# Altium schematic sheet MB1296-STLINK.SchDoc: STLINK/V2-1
size A4; Date: 25-JAN-2017; DocumentNumber: MB1296; Revision: D-01; SheetNumber: 3; SheetTotal: 6; Project: STM32 LoRa Discovery
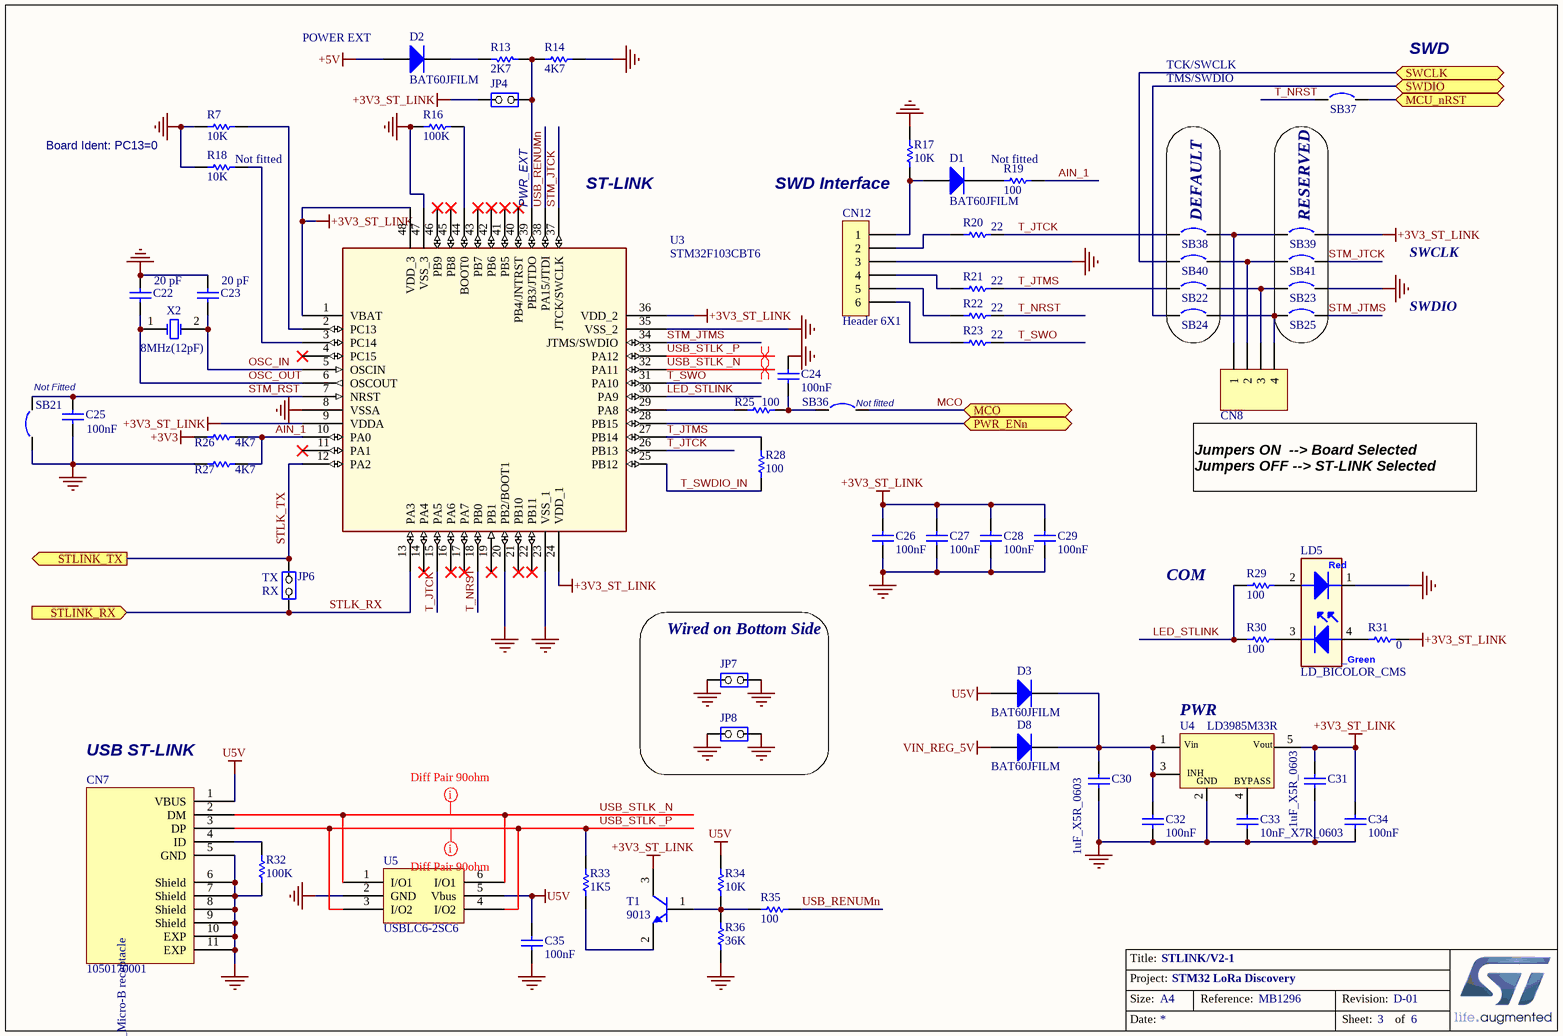
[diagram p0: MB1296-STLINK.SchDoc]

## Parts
C22  20 pF  [0603C]
C23  20 pF  [0603C]
C24  100nF  [0603C]
C25  100nF  [0603C]
C26  100nF  [0603C]
C27  100nF  [0603C]
C28  100nF  [0603C]
C29  100nF  [0603C]
C30  1uF_X5R_0603  [0603C]
C31  1uF_X5R_0603  [0603C]
C32  100nF  [0603C]
C33  10nF_X7R_0603  [0603C]
C34  100nF  [0603C]
C35  100nF  [0603C]
CN7  1050170001  [Molex_1050170001]
CN8  Header 4  [SIP4]  (value not drawn)
CN12  Header 6X1  [Header 1x6 Female (Wrapping)]
D1  BAT60JFILM  [SOD323/A]
D2  BAT60JFILM  [SOD323/A]
D3  BAT60JFILM  [SOD323/A]
D8  BAT60JFILM  [SOD323/A]
JP4  (no value)  [SIP2/2.54]
JP6  (no value)  [SIP2/2.54]
JP7  (no value)  [SIP2/2.54-BOT]
JP8  (no value)  [SIP2/2.54-BOT]
LD5  LD_BICOLOR_CMS  [LED SMD HSMF-A201-A00J1]
R7  10K  [0603]
R13  2K7  [0603]
R14  4K7  [0603]
R16  100K  [0603]
R17  10K  [0603]
R18  10K  [0603]
R19  100  [0603]
R20  22  [0603]
R21  22  [0603]
R22  22  [0603]
R23  22  [0603]
R25  100  [0603]
R26  4K7  [0603]
R27  4K7  [0603]
R28  100  [0603]
R29  100  [0603]
R30  100  [0603]
R31  0  [0603]
R32  100K  [0603]
R33  1K5  [0603]
R34  10K  [0603]
R35  100  [0603]
R36  36K  [0603]
SB21  Circuit Breaker  [JP2_SMD]  (value not drawn)
SB22  Circuit Breaker  [JP2_SMD]  (value not drawn)
SB23  Circuit Breaker  [SB-tiny]  (value not drawn)
SB24  Circuit Breaker  [JP2_SMD]  (value not drawn)
SB25  Circuit Breaker  [SB-tiny]  (value not drawn)
SB36  Circuit Breaker  [JP2_SMD]  (value not drawn)
SB37  Circuit Breaker  [JP2_SMD]  (value not drawn)
SB38  Circuit Breaker  [JP2_SMD]  (value not drawn)
SB39  Circuit Breaker  [SB-tiny]  (value not drawn)
SB40  Circuit Breaker  [JP2_SMD]  (value not drawn)
SB41  Circuit Breaker  [SB-tiny]  (value not drawn)
T1  9013  [SOT-23]
U3  STM32F103CBT6  [QFP48 7X7]
U4  LD3985M33R  [SOT-23-5L]
U5  USBLC6-2SC6  [SOT23-6L]
X2  8MHz(12pF)  [CRY_NX3225GD_2P]

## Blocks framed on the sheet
DEFAULT: SB22 SB24 SB38 SB40
RESERVED: SB23 SB25 SB39 SB41
Wired on Bottom Side: JP7 JP8

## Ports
MCO, MCU_nRST, PWR_ENn (bidir), STLINK_RX (in), STLINK_TX (out), SWCLK, SWDIO

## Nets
+3V3: R26.1
+3V3_ST_LINK: C26.2 C27.2 C28.2 C29.2 C31.2 C34.2 JP4.1(COMMON) R31.2 SB39.2 T1.3(C) U3.1(VBAT) U3.9(VDDA) U3.24(VDD_1) U3.36(VDD_2) U3.48(VDD_3) U4.5(Vout)
+5V: D2.1(A)
GND: C22.2 C23.2 C24.2 C25.1 C26.1 C27.1 C28.1 C29.1 C30.1 C31.1 C32.1 C33.1 C34.1 C35.1 CN7.5(GND) CN7.6(Shield) CN7.7(Shield) CN7.8(Shield) CN7.9(Shield) CN7.10(EXP) CN7.11(EXP) CN12.3 JP7.1(COMMON) JP7.2(NO) JP8.1(COMMON) JP8.2(NO) LD5.1 R7.2 R14.2 R16.2 R17.1 R18.2 R27.1 R32.1 R36.1 SB21.1 SB23.2 U3.8(VSSA) U3.20(PB2/BOOT1) U3.23(VSS_1) U3.35(VSS_2) U3.47(VSS_3) U4.2(GND) U5.2(GND)
U5V: C35.2 CN7.1(VBUS) D3.1(A) R34.1 U5.5(Vbus)
VIN_REG_5V: D8.1(A)
AIN_1: R19.1 R26.2 R27.2 U3.10(PA0)
LED_STLINK: R29.2 R30.2 U3.30(PA9)
MCO: SB36.2 ; port MCO
MCU_nRST: SB37.2 ; port MCU_nRST
OSC_IN: C23.1 U3.5(OSCIN) X2.2(OSC2)
OSC_OUT: C22.1 U3.6(OSCOUT) X2.1(OSC1)
PWR_ENn: U3.28(PB15) ; port PWR_ENn
STLK_RX: JP6.1(COMMON) U3.13(PA3) ; port STLINK_RX
STLK_TX: JP6.2(NO) U3.12(PA2) ; port STLINK_TX
STM_JTCK: SB41.2 U3.37(JTCK/SWCLK)
STM_JTMS: SB25.2 U3.34(JTMS/SWDIO)
STM_RST: C25.2 SB21.2 U3.7(NRST)
SWCLK: SB40.1 ; port SWCLK
SWDIO: SB24.1 ; port SWDIO
T_JTCK: R20.1 SB38.1 U3.15(PA5) U3.26(PB13)
T_JTMS: R21.1 R28.2 SB22.1 U3.27(PB14)
T_NRST: R22.1 SB37.1 U3.18(PB0)
T_SWDIO_IN: R28.1 U3.25(PB12)
T_SWO: R23.1 U3.31(PA10)
USB_RENUMn: R35.1 U3.38(PA15/JTDI)
USB_STLK _N: CN7.2(DM) U3.32(PA11) U5.1(I/O1) U5.6(I/O1)
USB_STLK _P: CN7.3(DP) R33.2 U3.33(PA12) U5.3(I/O2) U5.4(I/O2)
NetC24_1: C24.1 R25.1 SB36.1
NetC30_2: C30.2 C32.2 D3.2(K) D8.2(K) U4.1(Vin) U4.3(CE)
NetC33_2: C33.2 U4.4(BYPASS)
NetCN7_4: CN7.4(ID) R32.2
NetCN8_1: CN8.1 SB38.2 SB39.1
NetCN8_2: CN8.2 SB40.2 SB41.1
NetCN8_3: CN8.3 SB22.2 SB23.1
NetCN8_4: CN8.4 SB24.2 SB25.1
NetCN12_1: CN12.1 D1.1(A) R17.2
NetCN12_2: CN12.2 R20.2
NetCN12_4: CN12.4 R21.2
NetCN12_5: CN12.5 R22.2
NetCN12_6: CN12.6 R23.2
NetD1_2: D1.2(K) R19.2
NetD2_2: D2.2(K) R13.1
NetJP4_2: JP4.2(NO) R13.2 R14.1 U3.39(PB3/JTDO)
NetLD5_2: LD5.2 R29.1
NetLD5_3: LD5.3 R30.1
NetLD5_4: LD5.4 R31.1
NetR7_1: R7.1 U3.2(PC13)
NetR16_1: R16.1 U3.44(BOOT0)
NetR18_1: R18.1 U3.3(PC14)
NetR25_2: R25.2 U3.29(PA8)
NetR33_1: R33.1 T1.2(E)
NetR34_2: R34.2 R35.2 R36.2 T1.1(B)

Not connected (* = marked no-connect by the designer): U3 4(PC15)* 11(PA1)* 14(PA4)* 16(PA6)* 17(PA7)* 19(PB1)* 21(PB10)* 22(PB11)* 40(PB4/JNTRST)* 41(PB5)* 42(PB6)* 43(PB7)* 45(PB8)* 46(PB9)*

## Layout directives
differential pair: USB_STLK _N, USB_STLK _P
mark named Diff Pair 90ohm: USB_STLK _N, USB_STLK _P

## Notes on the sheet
- POWER EXT
- TCK/SWCLK
- TMS/SWDIO
- SWD
- Board Ident: PC13=0
- (near R18) Not fitted
- (near R19) Not fitted
- (near U3) PWR_EXT
- ST-LINK
- SWD Interface
- SWCLK
- SWDIO
- Not Fitted
- (near SB36) Not fitted
- Jumpers ON  --> Board Selected
  Jumpers OFF --> ST-LINK Selected
- (near JP6) TX
- COM
- (near JP6) RX
- (near U4) PWR
- (near CN7) USB ST-LINK

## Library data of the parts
C22 C23 = Capacitor_ST: Capacitor 0603; Manufacturer: YAGEO; Manufacturer P/N: CC0603JRNPO9BN200; Value: 20pF; Provided by: Subcon
C24-C29 C32 C34 C35 = CAP: Capacitor 100nF; Manufacturer: YAGEO; Manufacturer P/N: CC0603KRX7R9BB104; Provided by: Subcon
C30 C31 = CAP SMD 0603  X5R 1µF 25V 10%: 0603  X5R 1µF; Manufacturer: YAGEO; Manufacturer P/N: CC0603KRX5R7BB105; Provided by: Subcon
C33 = CAP SMD 0603  X7R 10000PF 50V 10%: 0603  X7R 10NF; Manufacturer: YAGEO; Manufacturer P/N: CC0603KRX7R9BB103; Order code RS: 2040779; Provided by: Subcon
CN7 = 1050170001: Silkscreen: USB
CN8 = Header 4: Header, 4-Pin, Single row; Manufacturer: Lyconn; Manufacturer P/N: 313140S111116; Provided by: Subcon
CN12 = Header 6X1: Header, 6-Pin, Single row; Manufacturer: Lyconn; Manufacturer P/N: 218106S1610; Provided by: Subcon
D1-D3 D8 = BAT60JFILM: Manufacturer: STM; ECCN_US/EU: EAR99/NEC; Provided by: ST
JP4 JP6-JP8 = JP2: Manufacturer: Lyconn; Manufacturer P/N: 313140S111116; Provided by: Subcon
LD5 = LD_BICOLOR_CMS: Bicolor Led; Manufacturer: everluck-led; Manufacturer P/N: LE-RGW35280; Provided by: Subcon
R7 R17 R34 = Resistor_ST: Resistor 0603; Manufacturer: YAGEO; Manufacturer P/N: RC0603JR-0710KL; Provided by: Subcon
R13 R36 = Res1: Resistor; Value: 1K
R14 R26 R27 = res1_4: Resistor; Manufacturer: YAGEO; Manufacturer P/N: RC0603FR-074K7L; Provided by: Subcon
R16 R32 = RES SMD 0603 100K 75V 5% 0.1W: 0603 100K 75V 5% 0.1W; Manufacturer: YAGEO; Manufacturer P/N: RC0603FR-07100KL; Provided by: Subcon
R18 = Resistor_ST: Resistor 0603; Manufacturer: YAGEO; Manufacturer P/N: RC0603JR-0710KL; Fitted: No; Provided by: Subcon
R19 = Res1_1: Resistor 0603; Manufacturer: YAGEO; Manufacturer P/N: RC0603FR-07100RL; Fitted: No; Provided by: Subcon; Value: 100R
R20-R23 = Res1_1: Resistor 0603; Manufacturer: YAGEO; Manufacturer P/N: RC0603FR-0722RL; Provided by: Subcon; Value: 100R
R25 R28-R30 R35 = Res1_1: Resistor 0603; Manufacturer: YAGEO; Manufacturer P/N: RC0603FR-07100RL; Provided by: Subcon; Value: 100R
R31 = Resistor_ST: Resistor 0402 / 0603 / 0805; Value: 10K
R33 = RES SMD 0603 100K 75V 5% 0.1W: 0603 1K5 75V 5% 0.1W; Manufacturer: YAGEO; Manufacturer P/N: RC0603FR-071K5L; Provided by: Subcon
SB21 SB23 SB25 SB36 SB39 SB41 = Circuit Breaker: Fitted: No
SB22 SB24 SB37 SB38 SB40 = Circuit Breaker: Fitted: Yes
T1 = NPN: NPN Bipolar Transistor; Manufacturer: STMicroelectronics; Manufacturer P/N: MMBT9013; ECCN_US/UE: EAR99/NEC; Provided by: STM
U3 = STM32F103CBT6: Medium-density performance line ARM-based 32-bit MCU with 64KB Flash; Manufacturer P/N: STM32F103C8T6; Manufacturer: STM; Ref STM: 9175981; Provided by: ST; ECCN_US/EU: 3A991A2/NEC
U4 = LD3985M33R: Ultra low drop-low noise BiCMOS voltage, regulators low ESR capacitors compatible; Manufacturer: STM; Ref St: 9176161; ECCN_US/EU: EAR99/NEC
U5 = USBLC6-2SC6: Manufacturer: STMicroelectronics; Manufacturer P/N: USBLC6-4SC6; ECCN_US/UE: EAR99/NEC; Provided by: STM
X2 = XTAL: Crystal Oscillator; Manufacturer: HongKongCrystal; Manufacturer P/N: 9SL8000012AFXHF0-SJ28; Provided by: Subcon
